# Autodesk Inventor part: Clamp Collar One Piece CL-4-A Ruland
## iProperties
Title: Clamp Collar One Piece CL-4-A Ruland
Author: cdotson
Shininess: 50.0
PropertySet Name: _Private Model Information
Created: 2001-02
Part Number: CL-4-A
Material: Aluminum-6061
Document SubType Name: Modeling
Designer: cdotson
Control State: 0
Master: False
Checked Out: False
PropertySet Name: Design Tracking Control
Density: 2.71
Volumn: 1.016368479534301
Area: 9.524446528983542
PropertySet Name: Model Information
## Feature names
1. Extrusion2
2. Extrusion3
3. Hole1
4. Extrusion5
5. Fillet1
